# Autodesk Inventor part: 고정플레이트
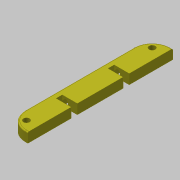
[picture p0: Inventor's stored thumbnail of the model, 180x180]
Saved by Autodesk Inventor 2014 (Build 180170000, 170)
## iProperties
Created: 2018-08
Part Number: 고정플레이트
Material: ABS 플라스틱
Document SubType Name: Modeling
Designer: mduedu
Density: 1.06 g/cm^3
Appearance: 밝은 황색
Mass: 13.199 g
Surface Area: 67.9758 cm^2
Volume: 12.4519 cm^3
Author: mduedu
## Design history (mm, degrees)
sketch "스케치1"
  geometry: L1 (0, -60)-(17, -60); L2 (17, -60)-(17, 60); L3 (17, 60)-(0, 60); L4 (0, 60)-(0, -60); 2 further points
  constraints: 8 end point, 2 parallel, 1 coincident, 1 horizontal, 1 midpoint, 1 perpendicular
  dimensions: "d0" = 120 distance between parallel lines of L3 L1; "d2" = 17 distance of L1.start L1.end
extrude "돌출1" new body sketch "스케치1" distance "d3" = 8; taper "d4" = 0 deg
fillet "모깎기1" dims "d5" = 15
fillet "모깎기2" dims "d6" = 1
sketch "스케치2"
  geometry: L1 (-17, 0)-(-17, 7) reference; L2 (0, 0)-(-17, 0) reference; L3 (-12.5, 4)-(-12.5, 0); L4 (-7.5, 4)-(-7.5, 0); A1 r 2.5 centre (-10, 4) between (-12.5, 4) and (-7.5, 4)
  constraints: 4 end point, 2 perpendicular, 2 point on circle, 2 point on line, 2 tangent, 1 centre point
  dimensions: "d7" = 5 diameter of A1; "d8" = 7 distance from line of A1.centre L1; "d9" = 4 distance from line of L2 A1.centre
extrude "돌출2" cut sketch "스케치2" stored distance "d10" = 70; taper "d11" = 0 deg
fillet "모깎기3" dims "d12" = 2.5
sketch "스케치3"
  geometry: L1 (-12.5, -19)-(0, -19); L2 (0, -19)-(0, -24); L3 (0, -24)-(-12.5, -24); L4 (-12.5, -24)-(-12.5, -19); L5 (0, -59)-(0, 59) reference; L6 (-17, 45)-(-17, -45) reference; 2 further points
  constraints: 8 end point, 2 parallel, 1 horizontal, 1 midpoint, 1 perpendicular, 1 vertical alignment
  dimensions: "d13" = 4.5 distance between parallel lines of L4 L6; "d14" = 19 distance from line of L1 point (0, 0); "d15" = 5 distance of L1.end L2.end
extrude "돌출3" cut sketch "스케치3" stored distance "d16" = 70; taper "d17" = 0 deg
sketch "스케치4"
  geometry: A1 r 15 centre (-2, -45) between (-17, -45) and (-2, -60) reference; A2 r 15 centre (-2, 45) between (-2, 60) and (-17, 45) reference; A3 r 10 centre (-2, 45) between (-2, 55) and (-12, 45); A4 r 10 centre (-2, -45) between (-12, -45) and (-2, -55); 3 further points
  constraints: 6 point on circle, 2 centre point, 2 horizontal alignment, 2 vertical alignment
  dimensions: "d18" = 5 radial gap between concentric circles of A3 A2; "d19" = 5 radial gap between concentric circles of A1 A4
hole "구멍1" sketch "스케치4" at (-9.071, 52.071), (-9.071, -52.071) diameter "d20" = 5; stored, may be unused: countersink angle "d24" = 90 deg, drill point angle "d26" = 118 deg; dims "d21" = 6, "d22" = 4, "d23" = 2, "d25" = 8
node "솔리드1"
mirror "대칭1"
